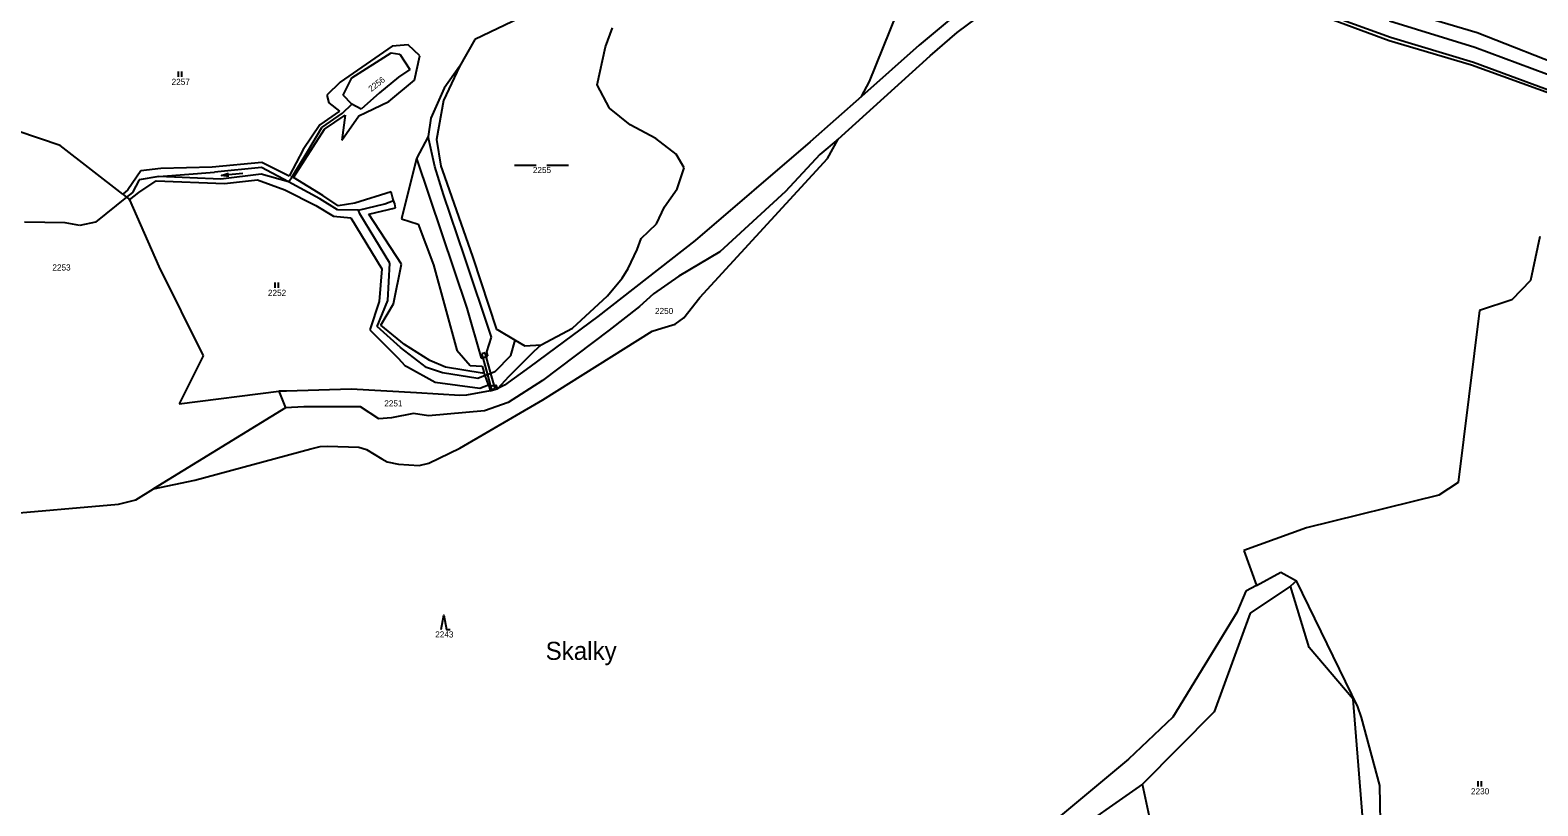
# Model space of a CAD drawing. Extents: x -609861 to -605046, y -1120287 to -1116307.
# Drawn here: x -606355 to -605937.2, y -1118754.8 to -1118539.7 of the extents above; entities that cross this region are included whole.
import ezdxf

# ---------------------------------------------------------------- set-up
doc = ezdxf.new("R2010")
doc.units = 0
for name, color, linetype in [('Vrstva 1', 7, 'Continuous'), ('Vrstva 2', 7, 'Continuous'), ('Vrstva 3', 7, 'Continuous'), ('Vrstva 4', 7, 'Continuous'), ('Vrstva 7', 7, 'Continuous')]:
    doc.layers.add(name, color=color, linetype=linetype)

msp = doc.modelspace()

# ---------------------------------------------------------------- linework, layer by layer
at = {"layer": 'Vrstva 1'}
for p, q in [((-606122.34, -1118553.98), (-606107.7, -1118517.29)), ((-606098.04, -1118540.41), (-606077.62, -1118525.06)), ((-605953.95, -1118540.43), (-605984.89, -1118531.19)), ((-606219.19, -1118536.27), (-606231.72, -1118542.28)), ((-606195.53, -1118544.33), (-606193.62, -1118539.04)), ((-606100.32, -1118536.96), (-606108.62, -1118543.9)), ((-605998.1, -1118535.27), (-605978.36, -1118542.57)), ((-606231.72, -1118542.28), (-606235.98, -1118549.82)), ((-606105.59, -1118546.88), (-606098.04, -1118540.41)), ((-605978.36, -1118542.57), (-605955.54, -1118549.33)), ((-605923, -1118552.65), (-605953.95, -1118540.43)), ((-606254.66, -1118544.21), (-606269.1, -1118554.12)), ((-606250.26, -1118543.81), (-606254.66, -1118544.21)), ((-606246.95, -1118546.82), (-606250.26, -1118543.81)), ((-606248.45, -1118553.55), (-606246.95, -1118546.82)), ((-606197.86, -1118554.93), (-606195.53, -1118544.33)), ((-606131.05, -1118569.95), (-606105.59, -1118546.88)), ((-606108.62, -1118543.9), (-606124.6, -1118558.12)), ((-606235.98, -1118549.82), (-606240.21, -1118555.84)), ((-605955.54, -1118549.33), (-605932.83, -1118557.54)), ((-606269.1, -1118554.12), (-606272.81, -1118557.72)), ((-606255.57, -1118559.49), (-606248.45, -1118553.55)), ((-606240.21, -1118555.84), (-606243.9, -1118564.17)), ((-606194.45, -1118561.34), (-606197.86, -1118554.93)), ((-606124.6, -1118558.12), (-606122.34, -1118553.98)), ((-606272.81, -1118557.72), (-606272.18, -1118559.88)), ((-606272.18, -1118559.88), (-606269.29, -1118562.21)), ((-606262, -1118562.56), (-606255.57, -1118559.49)), ((-606124.6, -1118558.12), (-606138.84, -1118570.67)), ((-606346.68, -1118571.71), (-606369.15, -1118564.07)), ((-606269.29, -1118562.21), (-606274.74, -1118566.02)), ((-606273.37, -1118567.14), (-606267.65, -1118563.32)), ((-606267.65, -1118563.32), (-606268.6, -1118570.2)), ((-606268.6, -1118570.2), (-606263.93, -1118563.47)), ((-606263.93, -1118563.47), (-606262, -1118562.56)), ((-606243.9, -1118564.17), (-606244.64, -1118569.22)), ((-606188.69, -1118566.01), (-606194.45, -1118561.34)), ((-606282.04, -1118580.56), (-606273.37, -1118567.14)), ((-606274.74, -1118566.02), (-606279.34, -1118572.79)), ((-606181.58, -1118569.73), (-606188.69, -1118566.01)), ((-606329.26, -1118585.2), (-606346.68, -1118571.71)), ((-606244.64, -1118569.22), (-606247.93, -1118575.34)), ((-606175.94, -1118574.1), (-606181.58, -1118569.73)), ((-606138.84, -1118570.67), (-606170.7, -1118598.04)), ((-606131.05, -1118569.95), (-606136.16, -1118574.18)), ((-606133.97, -1118575.31), (-606131.05, -1118569.95)), ((-606290.75, -1118576.46), (-606304.52, -1118577.71)), ((-606283.17, -1118580.18), (-606290.75, -1118576.46)), ((-606279.34, -1118572.79), (-606283.17, -1118580.18)), ((-606247.93, -1118575.34), (-606252.11, -1118592.08)), ((-606173.71, -1118577.91), (-606175.94, -1118574.1)), ((-606169.36, -1118613.89), (-606133.97, -1118575.31)), ((-606136.16, -1118574.18), (-606145.69, -1118584.47)), ((-606324.3, -1118578.71), (-606327.88, -1118584.02)), ((-606318.75, -1118578.1), (-606324.3, -1118578.71)), ((-606304.52, -1118577.71), (-606318.75, -1118578.1)), ((-606273.88, -1118585.61), (-606282.04, -1118580.56)), ((-606175.67, -1118583.69), (-606173.71, -1118577.91)), ((-606327.88, -1118584.02), (-606329.26, -1118585.2)), ((-606329.26, -1118585.2), (-606328.24, -1118585.99)), ((-606327.46, -1118586.82), (-606324.84, -1118584.78)), ((-606324.84, -1118584.78), (-606320.05, -1118581.54)), ((-606320.05, -1118581.54), (-606301.14, -1118582.2)), ((-606301.14, -1118582.2), (-606291.96, -1118581.2)), ((-606291.96, -1118581.2), (-606284.39, -1118583.98)), ((-606284.39, -1118583.98), (-606275.83, -1118588.33)), ((-606254.98, -1118584.58), (-606265.03, -1118587.68)), ((-606254.53, -1118586), (-606254.98, -1118584.58)), ((-606179.16, -1118588.73), (-606175.67, -1118583.69)), ((-606145.69, -1118584.47), (-606163.83, -1118601.23)), ((-606328.24, -1118585.99), (-606327.61, -1118586.48)), ((-606327.61, -1118586.48), (-606327.46, -1118586.82)), ((-606327.46, -1118586.82), (-606319.29, -1118605.28)), ((-606275.83, -1118588.33), (-606270.94, -1118591.33)), ((-606269.58, -1118588.42), (-606273.88, -1118585.61)), ((-606265.03, -1118587.68), (-606269.58, -1118588.42)), ((-606261.11, -1118590.77), (-606253.73, -1118588.99)), ((-606254.25, -1118586.94), (-606254.53, -1118586)), ((-606253.96, -1118587.89), (-606254.25, -1118586.94)), ((-606253.73, -1118588.99), (-606253.96, -1118587.89)), ((-606181.41, -1118593.41), (-606179.16, -1118588.73)), ((-606270.94, -1118591.33), (-606266.16, -1118591.78)), ((-606266.16, -1118591.78), (-606257.5, -1118605.93)), ((-606252.05, -1118604.58), (-606261.11, -1118590.77)), ((-606252.11, -1118592.08), (-606247.47, -1118593.55)), ((-606247.47, -1118593.55), (-606243.17, -1118604.82)), ((-606185.62, -1118597.46), (-606181.41, -1118593.41)), ((-606186.78, -1118600.51), (-606185.62, -1118597.46)), ((-605936.57, -1118596.93), (-605939.17, -1118609.14)), ((-606170.7, -1118598.04), (-606197.64, -1118619.08)), ((-606189.22, -1118605.83), (-606186.78, -1118600.51)), ((-606163.83, -1118601.23), (-606175.25, -1118607.9)), ((-606319.29, -1118605.28), (-606307.03, -1118630.01)), ((-606257.5, -1118605.93), (-606258.29, -1118615)), ((-606254.31, -1118615.63), (-606252.05, -1118604.58)), ((-606243.17, -1118604.82), (-606236.74, -1118628.44)), ((-606190.92, -1118608.47), (-606189.22, -1118605.83)), ((-606194.95, -1118613.41), (-606190.92, -1118608.47)), ((-606175.25, -1118607.9), (-606182.22, -1118612.84)), ((-605939.17, -1118609.14), (-605944.33, -1118614.47)), ((-606204.69, -1118622.34), (-606194.95, -1118613.41)), ((-606182.22, -1118612.84), (-606186.16, -1118616.37)), ((-606173.83, -1118619.48), (-606169.36, -1118613.89)), ((-605944.33, -1118614.47), (-605953.31, -1118617.45)), ((-606258.29, -1118615), (-606260.86, -1118622.79)), ((-606257.76, -1118621.56), (-606254.31, -1118615.63)), ((-606186.16, -1118616.37), (-606194.49, -1118622.89)), ((-605953.31, -1118617.45), (-605959.24, -1118665.17)), ((-606260.86, -1118622.79), (-606253.04, -1118630.67)), ((-606251.27, -1118626.92), (-606257.76, -1118621.56)), ((-606197.64, -1118619.08), (-606216.49, -1118633.12)), ((-606213.35, -1118626.97), (-606204.69, -1118622.34)), ((-606182.6, -1118623.15), (-606179.89, -1118622.35)), ((-606179.89, -1118622.35), (-606176.22, -1118621.24)), ((-606176.22, -1118621.24), (-606173.83, -1118619.48)), ((-606244.24, -1118631.34), (-606251.27, -1118626.92)), ((-606215.31, -1118628.76), (-606213.35, -1118626.97)), ((-606194.49, -1118622.89), (-606213.01, -1118636.86)), ((-606212.88, -1118642.23), (-606182.6, -1118623.15)), ((-606307.03, -1118630.01), (-606313.71, -1118643.29)), ((-606253.04, -1118630.67), (-606251.15, -1118632.71)), ((-606236.74, -1118628.44), (-606233, -1118632.71)), ((-606217.84, -1118631.19), (-606215.31, -1118628.76)), ((-606251.15, -1118632.71), (-606250.45, -1118633.08)), ((-606250.45, -1118633.08), (-606242.78, -1118637.34)), ((-606239.84, -1118633.21), (-606244.24, -1118631.34)), ((-606229.74, -1118634.87), (-606239.84, -1118633.21)), ((-606233, -1118632.71), (-606229.76, -1118632.92)), ((-606229.76, -1118632.92), (-606229.25, -1118634.43)), ((-606229.25, -1118634.43), (-606229.74, -1118634.87)), ((-606228.88, -1118635.52), (-606229.25, -1118634.43)), ((-606216.49, -1118633.12), (-606223.57, -1118638.15)), ((-606222.3, -1118635.79), (-606217.84, -1118631.19)), ((-606266.03, -1118639.27), (-606283.98, -1118639.79)), ((-606247.92, -1118640.28), (-606266.03, -1118639.27)), ((-606242.78, -1118637.34), (-606230.41, -1118638.99)), ((-606230.41, -1118638.99), (-606228, -1118638.1)), ((-606228, -1118638.1), (-606228.88, -1118635.52)), ((-606228, -1118638.1), (-606227.82, -1118638.61)), ((-606227.82, -1118638.61), (-606227.47, -1118639.77)), ((-606227.47, -1118639.77), (-606225.52, -1118639.15)), ((-606225.52, -1118639.15), (-606225.38, -1118639.11)), ((-606225.38, -1118639.11), (-606222.3, -1118635.79)), ((-606223.57, -1118638.15), (-606225.38, -1118639.11)), ((-606213.01, -1118636.86), (-606222.49, -1118643.01)), ((-606313.71, -1118643.29), (-606286.09, -1118639.83)), ((-606283.98, -1118639.79), (-606286.09, -1118639.83)), ((-606286.09, -1118639.83), (-606284.18, -1118644.43)), ((-606235.91, -1118641.01), (-606247.92, -1118640.28)), ((-606235.93, -1118655.64), (-606212.88, -1118642.23)), ((-606234.06, -1118640.97), (-606235.91, -1118641.01)), ((-606227.47, -1118639.77), (-606234.06, -1118640.97)), ((-606222.49, -1118643.01), (-606229.08, -1118645.25)), ((-606284.18, -1118644.43), (-606320.77, -1118666.93)), ((-606279.15, -1118644.2), (-606284.18, -1118644.43)), ((-606263.45, -1118644.17), (-606279.15, -1118644.2)), ((-606258.38, -1118647.52), (-606263.45, -1118644.17)), ((-606254.87, -1118647.23), (-606258.38, -1118647.52)), ((-606248.77, -1118646.06), (-606254.87, -1118647.23)), ((-606244.58, -1118646.64), (-606248.77, -1118646.06)), ((-606229.08, -1118645.25), (-606244.58, -1118646.64)), ((-606309.38, -1118664.5), (-606277.23, -1118655.79)), ((-606277.23, -1118655.79), (-606274.57, -1118655.15)), ((-606274.57, -1118655.15), (-606272.57, -1118655.07)), ((-606272.57, -1118655.07), (-606263.88, -1118655.39)), ((-606263.88, -1118655.39), (-606261.81, -1118656.03)), ((-606261.81, -1118656.03), (-606257.5, -1118658.59)), ((-606244.46, -1118659.79), (-606235.93, -1118655.64)), ((-606257.5, -1118658.59), (-606256.06, -1118659.38)), ((-606256.06, -1118659.38), (-606252.95, -1118660.1)), ((-606252.95, -1118660.1), (-606247.21, -1118660.42)), ((-606247.21, -1118660.42), (-606244.46, -1118659.79)), ((-606320.77, -1118666.93), (-606309.38, -1118664.5)), ((-606325.68, -1118669.95), (-606320.77, -1118666.93)), ((-605964.59, -1118668.66), (-606001.23, -1118677.74)), ((-605959.24, -1118665.17), (-605964.59, -1118668.66)), ((-606403.03, -1118677.6), (-606330.49, -1118671.12)), ((-606330.49, -1118671.12), (-606325.68, -1118669.95)), ((-606001.23, -1118677.74), (-606018.59, -1118684)), ((-606018.59, -1118684), (-606015.16, -1118693.7)), ((-606015.16, -1118693.7), (-606018.06, -1118695.29)), ((-606015.16, -1118693.7), (-606008.4, -1118690)), ((-606008.4, -1118690), (-606004.04, -1118692.4)), ((-606004.04, -1118692.4), (-606005.67, -1118693.88)), ((-605987.01, -1118727.36), (-606004.04, -1118692.4)), ((-606018.06, -1118695.29), (-606020.54, -1118701.23)), ((-606005.67, -1118693.88), (-606016.88, -1118701.37)), ((-606000.49, -1118710.9), (-606005.67, -1118693.88)), ((-606020.54, -1118701.23), (-606038.27, -1118730.24)), ((-606016.88, -1118701.37), (-606026.87, -1118728.76)), ((-605988.38, -1118725.22), (-606000.49, -1118710.9)), ((-605982.66, -1118794.77), (-605988.38, -1118725.22)), ((-606038.27, -1118730.24), (-606050.56, -1118741.88)), ((-606026.87, -1118728.76), (-606046.73, -1118748.8)), ((-605986.05, -1118730.3), (-605987.01, -1118727.36)), ((-605980.92, -1118749.15), (-605986.05, -1118730.3)), ((-606050.56, -1118741.88), (-606072.23, -1118759.88)), ((-606046.73, -1118748.8), (-606068.61, -1118764.15)), ((-606042.06, -1118770.63), (-606046.73, -1118748.8)), ((-605980.43, -1118783.26), (-605980.92, -1118749.15))]:
    msp.add_line(p, q, dxfattribs=at)
at = {"layer": 'Vrstva 3'}
for p, q in [((-606313.95, -1118551.2), (-606313.95, -1118552.7)), ((-606312.95, -1118552.7), (-606312.95, -1118551.2)), ((-606296.022, -1118579.492), (-606301.998, -1118580.028)), ((-606220.77, -1118577.15), (-606214.77, -1118577.15)), ((-606211.77, -1118577.15), (-606205.77, -1118577.15)), ((-606287.15, -1118609.71), (-606287.15, -1118611.21)), ((-606286.15, -1118611.21), (-606286.15, -1118609.71)), ((-605953.76, -1118747.91), (-605953.76, -1118749.41)), ((-605952.76, -1118749.41), (-605952.76, -1118747.91))]:
    msp.add_line(p, q, dxfattribs=at)
for points in [[(-606299.961, -1118580.347), (-606301.998, -1118580.028), (-606300.051, -1118579.351)], [(-606241.08, -1118705.92), (-606240.33, -1118701.92), (-606239.58, -1118705.92), (-606238.58, -1118705.92)]]:
    msp.add_lwpolyline(points, dxfattribs=at)
at = {"layer": 'Vrstva 4'}
for p, q in [((-605997.96, -1118534.49), (-605977.97, -1118541.69)), ((-605954.58, -1118544.51), (-605978.27, -1118537.26)), ((-605977.97, -1118541.69), (-605955.03, -1118548.57)), ((-606265.81, -1118552.96), (-606254.93, -1118545.98)), ((-606254.93, -1118545.98), (-606252.58, -1118546.37)), ((-606252.58, -1118546.37), (-606249.78, -1118550.63)), ((-605930.79, -1118553.38), (-605954.58, -1118544.51)), ((-606249.78, -1118550.63), (-606252.93, -1118552.75)), ((-606235.98, -1118549.82), (-606240.39, -1118559.21)), ((-605955.03, -1118548.57), (-605932.7, -1118556.79)), ((-606268.21, -1118557.74), (-606265.81, -1118552.96)), ((-606252.93, -1118552.75), (-606258.13, -1118557.13)), ((-606265.87, -1118560.21), (-606268.21, -1118557.74)), ((-606258.13, -1118557.13), (-606263.29, -1118561.64)), ((-606240.39, -1118559.21), (-606242.33, -1118570.09)), ((-606274.13, -1118566.74), (-606268.46, -1118562.72)), ((-606268.46, -1118562.72), (-606265.87, -1118560.21)), ((-606263.29, -1118561.64), (-606265.87, -1118560.21)), ((-606277.99, -1118573.24), (-606274.13, -1118566.74)), ((-606242.85, -1118577.52), (-606244.64, -1118569.22)), ((-606242.33, -1118570.09), (-606241.21, -1118577.42)), ((-606282.58, -1118580.63), (-606277.99, -1118573.24)), ((-606247.93, -1118575.34), (-606234, -1118616.82)), ((-606319.3, -1118580.28), (-606324.76, -1118581.25)), ((-606319.3, -1118580.28), (-606303.89, -1118579.12)), ((-606302.15, -1118581.07), (-606319.3, -1118580.28)), ((-606290.85, -1118577.77), (-606303.89, -1118579.12)), ((-606291, -1118579.68), (-606302.15, -1118581.07)), ((-606283.4, -1118581.76), (-606291, -1118579.68)), ((-606283.4, -1118581.76), (-606290.85, -1118577.77)), ((-606283.4, -1118581.76), (-606282.58, -1118580.63)), ((-606240.46, -1118585.27), (-606242.85, -1118577.52)), ((-606241.21, -1118577.42), (-606240.76, -1118578.46)), ((-606240.76, -1118578.46), (-606232.27, -1118602.8)), ((-606326.64, -1118584.7), (-606328.24, -1118585.99)), ((-606324.76, -1118581.25), (-606326.64, -1118584.7)), ((-606274.75, -1118586.46), (-606283.4, -1118581.76)), ((-606328.24, -1118585.99), (-606336.84, -1118592.96)), ((-606269.82, -1118589.57), (-606274.75, -1118586.46)), ((-606264.03, -1118589.67), (-606256.65, -1118587.86)), ((-606256.65, -1118587.86), (-606254.25, -1118586.94)), ((-606234.57, -1118602.49), (-606240.46, -1118585.27)), ((-606345.31, -1118593.11), (-606356.51, -1118592.98)), ((-606341.22, -1118593.92), (-606345.31, -1118593.11)), ((-606336.84, -1118592.96), (-606341.22, -1118593.92)), ((-606264.03, -1118589.67), (-606269.82, -1118589.57)), ((-606263.58, -1118590.7), (-606264.03, -1118589.67)), ((-606255.31, -1118604.31), (-606263.58, -1118590.7)), ((-606255.84, -1118614.73), (-606255.31, -1118604.31)), ((-606227.16, -1118624.81), (-606234.57, -1118602.49)), ((-606232.27, -1118602.8), (-606225.77, -1118622.75)), ((-606258.83, -1118621.92), (-606255.84, -1118614.73)), ((-606234, -1118616.82), (-606229.97, -1118630.7)), ((-606252.34, -1118627.73), (-606258.83, -1118621.92)), ((-606225.77, -1118622.75), (-606225.4, -1118622.86)), ((-606228.45, -1118628.95), (-606227.16, -1118624.81)), ((-606225.4, -1118622.86), (-606220.58, -1118625.7)), ((-606221.77, -1118629.98), (-606220.58, -1118625.7)), ((-606220.58, -1118625.7), (-606217.93, -1118627.26)), ((-606217.93, -1118627.26), (-606213.35, -1118626.97)), ((-606245.15, -1118633.24), (-606252.34, -1118627.73)), ((-606229.97, -1118630.7), (-606229.56, -1118630.56)), ((-606228.9, -1118629.21), (-606229.85, -1118629.49)), ((-606229.85, -1118629.49), (-606229.56, -1118630.56)), ((-606229.56, -1118630.56), (-606228.61, -1118630.25)), ((-606229.56, -1118630.56), (-606228.26, -1118635.28)), ((-606228.61, -1118630.25), (-606228.9, -1118629.21)), ((-606228.61, -1118630.25), (-606228.13, -1118630.09)), ((-606227.32, -1118634.91), (-606228.61, -1118630.25)), ((-606228.13, -1118630.09), (-606228.45, -1118628.95)), ((-606221.77, -1118629.98), (-606226.24, -1118634.48)), ((-606240.7, -1118634.72), (-606245.15, -1118633.24)), ((-606230.94, -1118636.33), (-606240.7, -1118634.72)), ((-606228.26, -1118635.28), (-606228.88, -1118635.52)), ((-606227.32, -1118634.91), (-606228.26, -1118635.28)), ((-606228.26, -1118635.28), (-606227.38, -1118638.48)), ((-606226.24, -1118634.48), (-606227.32, -1118634.91)), ((-606226.41, -1118638.18), (-606227.32, -1118634.91)), ((-606228.88, -1118635.52), (-606230.94, -1118636.33)), ((-606227.82, -1118638.61), (-606227.38, -1118638.48)), ((-606227.38, -1118638.48), (-606226.41, -1118638.18)), ((-606227.38, -1118638.48), (-606227.14, -1118639.36)), ((-606227.14, -1118639.36), (-606226.15, -1118639.13)), ((-606226.41, -1118638.18), (-606225.94, -1118638.04)), ((-606226.15, -1118639.13), (-606226.41, -1118638.18)), ((-606225.94, -1118638.04), (-606225.52, -1118639.15))]:
    msp.add_line(p, q, dxfattribs=at)

# ---------------------------------------------------------------- texts
at = {"layer": 'Vrstva 2'}
for s, p in [('2257', (-606315.783, -1118554.9)), ('2255', (-606215.673, -1118579.35)), ('2253', (-606348.823, -1118606.37)), ('2252', (-606289.083, -1118613.41)), ('2250', (-606181.823, -1118618.44)), ('2251', (-606256.853, -1118644.06)), ('2243', (-606242.733, -1118708.12)), ('2230', (-605955.683, -1118751.61))]:
    msp.add_text(s, height=1.7, dxfattribs=at).set_placement(p)
msp.add_text('2256', height=1.7, rotation=38.10169, dxfattribs=at).set_placement((-606260.433, -1118556.914))
at = {"layer": 'Vrstva 7'}
msp.add_text('Skalky', height=5, dxfattribs=at).set_placement((-606212.129, -1118714.32))

doc.saveas('drawing.dxf')
